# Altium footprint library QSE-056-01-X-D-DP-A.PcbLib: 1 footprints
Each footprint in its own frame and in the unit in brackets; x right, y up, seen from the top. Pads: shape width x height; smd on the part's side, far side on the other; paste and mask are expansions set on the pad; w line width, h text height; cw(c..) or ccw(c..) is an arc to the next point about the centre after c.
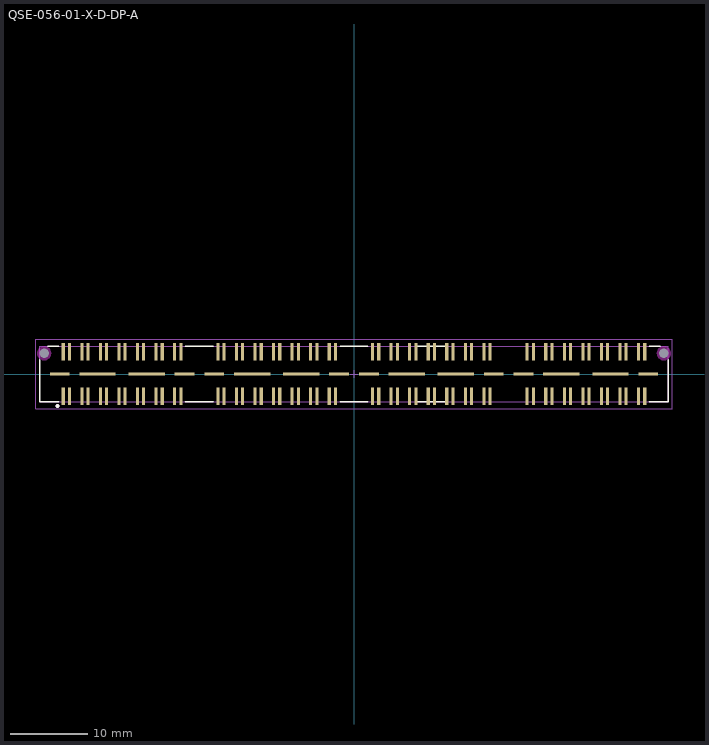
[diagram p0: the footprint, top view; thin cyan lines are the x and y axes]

## QSE-056-01-X-D-DP-A [mm] "0.80mm pitch, 112 pin, high speed socket strip; differential"
height 3.25
pads (130):
  rect 0.4x2.25 smd mask+0: 1(-37.6,-2.87) 2(-37.6,2.87) 3(-36.8,-2.87) 4(-36.8,2.87) 5(-35.2,-2.87) 6(-35.2,2.87) 7(-34.4,-2.87) 8(-34.4,2.87) 9(-32.8,-2.87) 10(-32.8,2.87) 11(-32,-2.87) 12(-32,2.87) 13(-30.4,-2.87) 14(-30.4,2.87) 15(-29.6,-2.87) 16(-29.6,2.87) 17(-28,-2.87) 18(-28,2.87) 19(-27.2,-2.87) 20(-27.2,2.87) 21(-25.6,-2.87) 22(-25.6,2.87) 23(-24.8,-2.87) 24(-24.8,2.87) 25(-23.2,-2.87) 26(-23.2,2.87) 27(-22.4,-2.87) 28(-22.4,2.87) 29(-17.6,-2.87) 30(-17.6,2.87) 31(-16.8,-2.87) 32(-16.8,2.87) 33(-15.2,-2.87) 34(-15.2,2.87) 35(-14.4,-2.87) 36(-14.4,2.87) 37(-12.8,-2.87) 38(-12.8,2.87) 39(-12,-2.87) 40(-12,2.87) 41(-10.4,-2.87) 42(-10.4,2.87) 43(-9.6,-2.87) 44(-9.6,2.87) 45(-8,-2.87) 46(-8,2.87) 47(-7.2,-2.87) 48(-7.2,2.87) 49(-5.6,-2.87) 50(-5.6,2.87) 51(-4.8,-2.87) 52(-4.8,2.87) 53(-3.2,-2.87) 54(-3.2,2.87) 55(-2.4,-2.87) 56(-2.4,2.87) 57(2.4,-2.87) 58(2.4,2.87) 59(3.2,-2.87) 60(3.2,2.87) 61(4.8,-2.87) 62(4.8,2.87) 63(5.6,-2.87) 64(5.6,2.87) 65(7.2,-2.87) 66(7.2,2.87) 67(8,-2.87) 68(8,2.87) 69(9.6,-2.87) 70(9.6,2.87) 71(10.4,-2.87) 72(10.4,2.87) 73(12,-2.87) 74(12,2.87) 75(12.8,-2.87) 76(12.8,2.87) 77(14.4,-2.87) 78(14.4,2.87) 79(15.2,-2.87) 80(15.2,2.87) 81(16.8,-2.87) 82(16.8,2.87) 83(17.6,-2.87) 84(17.6,2.87) 85(22.4,-2.87) 86(22.4,2.87) 87(23.2,-2.87) 88(23.2,2.87) 89(24.8,-2.87) 90(24.8,2.87) 91(25.6,-2.87) 92(25.6,2.87) 93(27.2,-2.87) 94(27.2,2.87) 95(28,-2.87) 96(28,2.87) 97(29.6,-2.87) 98(29.6,2.87) 99(30.4,-2.87) 100(30.4,2.87) 101(32,-2.87) 102(32,2.87) 103(32.8,-2.87) 104(32.8,2.87) 105(34.4,-2.87) 106(34.4,2.87) 107(35.2,-2.87) 108(35.2,2.87) 109(36.8,-2.87) 110(36.8,2.87) 111(37.6,-2.87) 112(37.6,2.87)
  rect 2.55x0.45 smd mask+0: 113(-38.065,0) 116(-21.935,0) 117(-18.065,0) 120(-1.935,0) 121(1.935,0) 124(18.065,0) 125(21.935,0) 128(38.065,0)
  rect 4.7x0.45 smd mask+0: 114(-33.175,0) 115(-26.825,0) 118(-13.175,0) 119(-6.825,0) 122(6.825,0) 123(13.175,0) 126(26.825,0) 127(33.175,0)
  round 1 hole 1.2 unplated mask+0: 129(-40.065,2.67) 130(40.065,2.67)
Top Overlay:
  circle w0.25: c-38.35,-4.15 r0.125
  lines w0.2: -40.65,1.85 -40.65,-3.6 -38.2,-3.6 ; -39.6,3.6 -38.2,3.6 ; -21.8,-3.6 -18.2,-3.6 ; -21.8,3.6 -18.2,3.6 ; -1.8,-3.6 1.8,-3.6 ; -1.8,3.6 1.8,3.6 ; 8.2,-3.6 11.8,-3.6 ; 8.2,3.6 11.8,3.6 ; 38.2,-3.6 40.65,-3.6 40.65,1.85 ; 38.2,3.6 39.6,3.6
Keep-Out Layer:
  pour cut-out: -39.157,2.67 -39.188,2.905 -39.279,3.124 -39.423,3.312 -39.611,3.456 -39.83,3.547 -40.065,3.578 -40.3,3.547 -40.519,3.456 -40.707,3.312 -40.851,3.124 -40.942,2.905 -40.973,2.67 -40.942,2.435 -40.851,2.216 -40.707,2.028 -40.519,1.884 -40.3,1.793 -40.065,1.762 -39.83,1.793 -39.611,1.884 -39.423,2.028 -39.279,2.216 -39.188,2.435
  pour cut-out: 40.973,2.67 40.942,2.905 40.851,3.124 40.707,3.312 40.519,3.456 40.3,3.547 40.065,3.578 39.83,3.547 39.611,3.456 39.423,3.312 39.279,3.124 39.188,2.905 39.157,2.67 39.188,2.435 39.279,2.216 39.423,2.028 39.611,1.884 39.83,1.793 40.065,1.762 40.3,1.793 40.519,1.884 40.707,2.028 40.851,2.216 40.942,2.435
Mechanical 12:
  lines w0.001: -40.65,-3.6 -40.65,3.6 40.65,3.6 40.65,-3.6 -40.65,-3.6
Mechanical 13:
  circle w0.25: c-38.35,-4.15 r0.125
  lines w0.1: -40.65,-3.6 -40.65,3.6 40.65,3.6 40.65,-3.6 -40.65,-3.6
  text ".Designator" at 0.254,0.254 h1.52
Mechanical 15:
  lines w0.05: -0.5,0 0.5,0 ; 0,-0.5 0,0.5 ; -41.15,-4.5 -41.15,4.5 41.15,4.5 41.15,-4.5 -41.15,-4.5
